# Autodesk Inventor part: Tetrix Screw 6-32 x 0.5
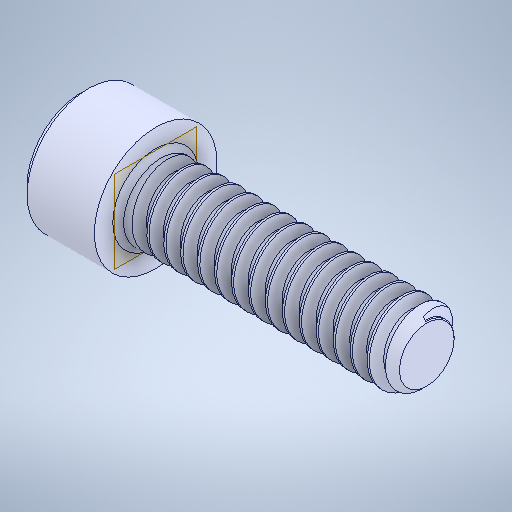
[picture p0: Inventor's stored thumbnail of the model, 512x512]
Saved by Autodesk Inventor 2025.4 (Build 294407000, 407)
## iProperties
Created: 2021-10
Part Number: Tetrix Screw 6-32 x 0.5
Material: Genérico
Document SubType Name: Modeling
Designer: usuario
Density: 1 g/cm^3
Appearance: Valor por defecto
Author: usuario
Sending System: SolidWorks 2016
Last Author: LENOVO
Last Saved: 2021-10-22
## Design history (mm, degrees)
fillet "Fillet1"
node "Plane1"
node "Sólido1"
